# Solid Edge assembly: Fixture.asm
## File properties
Author: Sarvanan
Template: sync ansi assembly.asm
Last saved by: Cadcim
Revision: 3
Application: Solid Edge
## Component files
end plate.par
disk.par
support pin.par
spacer.par
center pin.par
bolt.par
nut.par
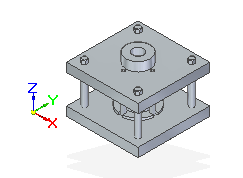
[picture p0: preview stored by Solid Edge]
